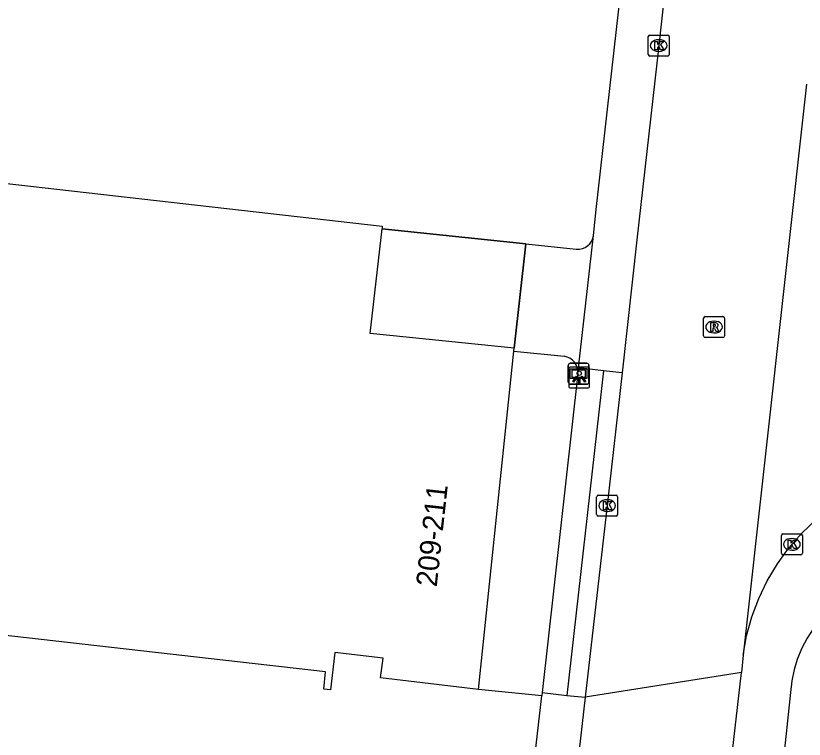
# Model space of a CAD drawing. Extents: x 161389 to 162585, y 388479 to 389761.
# Drawn here: x 162316.81 to 162354.51, y 388781.78 to 388816.39 of the extents above; entities that cross this region are included whole.
import ezdxf

# ---------------------------------------------------------------- set-up
doc = ezdxf.new("R2010")
doc.units = 0
for name, color, linetype in [('IMGEO_Berm_groen', 7, 'Continuous'), ('IMGEO_Groenvoorziening', 7, 'Continuous'), ('IMGEO_Hek', 7, 'Continuous'), ('IMGEO_Kolk', 7, 'Continuous'), ('IMGEO_Lichtpunt', 7, 'Continuous'), ('IMGEO_Pand', 7, 'Continuous'), ('IMGEO_Pand_nummerreeks', 7, 'Continuous'), ('IMGEO_Rijbaan_lokaal_gesloten', 7, 'Continuous'), ('IMGEO_Rioolput', 7, 'Continuous'), ('IMGEO_Verklikker', 7, 'Continuous'), ('IMGEO_Voetpad_open', 7, 'Continuous')]:
    doc.layers.add(name, color=color, linetype=linetype)

msp = doc.modelspace()

# ---------------------------------------------------------------- linework, layer by layer
at = {"layer": 'IMGEO_Berm_groen'}
msp.add_lwpolyline([(162353.858, 388784.024), (162350.241, 388750), (162349.171, 388742.638), (162348.615, 388740.14)], dxfattribs=at)
msp.add_arc((162359.605, 388783.689), 5.757, 90.5023, 176.6641, dxfattribs=at)
at = {"layer": 'IMGEO_Groenvoorziening'}
msp.add_lwpolyline([(162341.961, 388783.856), (162338.936, 388784.171)], dxfattribs=at)
at = {"layer": 'IMGEO_Hek'}
for points in [[(162341.192, 388805.477), (162334.321, 388806.194)], [(162340.638, 388800.493), (162341.192, 388805.477)]]:
    msp.add_lwpolyline(points, dxfattribs=at)
at = {"layer": 'IMGEO_Kolk'}
for p, q in [((162347.048, 388814.54), (162347.048, 388815.392)), ((162347.123, 388815.466), (162347.975, 388815.466)), ((162348.049, 388815.392), (162348.049, 388814.54)), ((162347.536, 388815.246), (162347.561, 388815.246)), ((162347.559, 388814.686), (162347.534, 388814.686)), ((162347.975, 388814.466), (162347.123, 388814.466)), ((162344.582, 388792.535), (162344.582, 388793.387)), ((162344.657, 388793.461), (162345.509, 388793.461)), ((162345.07, 388793.241), (162345.095, 388793.241)), ((162345.583, 388793.387), (162345.583, 388792.535)), ((162345.509, 388792.461), (162344.657, 388792.461)), ((162345.093, 388792.681), (162345.068, 388792.681)), ((162353.416, 388790.681), (162353.416, 388791.533)), ((162353.491, 388791.607), (162354.343, 388791.607)), ((162353.904, 388791.387), (162353.929, 388791.387)), ((162354.417, 388791.533), (162354.417, 388790.681)), ((162354.343, 388790.607), (162353.491, 388790.607)), ((162353.927, 388790.827), (162353.902, 388790.827))]:
    msp.add_line(p, q, dxfattribs=at)
for points in [[(162347.048, 388814.54), (162347.048, 388815.392)], [(162347.123, 388815.466), (162347.975, 388815.466)], [(162348.049, 388815.392), (162348.049, 388814.54)], [(162347.369, 388815.166), (162347.492, 388815.166), (162347.492, 388815.015), (162347.622, 388815.166), (162347.786, 388815.166), (162347.64, 388815.015), (162347.793, 388814.766), (162347.641, 388814.766), (162347.556, 388814.93), (162347.492, 388814.863), (162347.492, 388814.766), (162347.369, 388814.766), (162347.369, 388815.166)], [(162347.975, 388814.466), (162347.123, 388814.466)], [(162344.582, 388792.535), (162344.582, 388793.387)], [(162344.657, 388793.461), (162345.509, 388793.461)], [(162344.903, 388793.161), (162345.026, 388793.161), (162345.026, 388793.01), (162345.156, 388793.161), (162345.32, 388793.161), (162345.174, 388793.01), (162345.327, 388792.761), (162345.175, 388792.761), (162345.09, 388792.925), (162345.026, 388792.858), (162345.026, 388792.761), (162344.903, 388792.761), (162344.903, 388793.161)], [(162345.583, 388793.387), (162345.583, 388792.535)], [(162345.509, 388792.461), (162344.657, 388792.461)], [(162353.416, 388790.681), (162353.416, 388791.533)], [(162353.491, 388791.607), (162354.343, 388791.607)], [(162353.737, 388791.307), (162353.86, 388791.307), (162353.86, 388791.156), (162353.99, 388791.307), (162354.154, 388791.307), (162354.008, 388791.156), (162354.161, 388790.907), (162354.009, 388790.907), (162353.924, 388791.071), (162353.86, 388791.004), (162353.86, 388790.907), (162353.737, 388790.907), (162353.737, 388791.307)], [(162354.417, 388791.533), (162354.417, 388790.681)], [(162354.343, 388790.607), (162353.491, 388790.607)]]:
    msp.add_lwpolyline(points, dxfattribs=at)
for centre, start, end in [((162347.125, 388815.39), 91.552, 178.448), ((162347.125, 388815.39), 91.552, 178.448), ((162347.973, 388815.39), 1.552, 88.448), ((162347.973, 388815.39), 1.552, 88.448), ((162347.125, 388814.542), 181.552, 268.448), ((162347.125, 388814.542), 181.552, 268.448), ((162347.973, 388814.542), 271.552, 358.448), ((162347.973, 388814.542), 271.552, 358.448), ((162344.659, 388793.385), 91.552, 178.448), ((162344.659, 388793.385), 91.552, 178.448), ((162345.507, 388793.385), 1.552, 88.448), ((162345.507, 388793.385), 1.552, 88.448), ((162344.659, 388792.537), 181.552, 268.448), ((162344.659, 388792.537), 181.552, 268.448), ((162345.507, 388792.537), 271.552, 358.448), ((162345.507, 388792.537), 271.552, 358.448), ((162353.493, 388791.531), 91.552, 178.448), ((162353.493, 388791.531), 91.552, 178.448), ((162354.341, 388791.531), 1.552, 88.448), ((162354.341, 388791.531), 1.552, 88.448), ((162353.493, 388790.683), 181.552, 268.448), ((162353.493, 388790.683), 181.552, 268.448), ((162354.341, 388790.683), 271.552, 358.448), ((162354.341, 388790.683), 271.552, 358.448)]:
    msp.add_arc(centre, 0.0765, start, end, dxfattribs=at)
for centre, major_axis, ratio, start_param, end_param in [((162347.535, 388814.966), (-0.387, 0.002), 0.722429, 4.712389, 7.853982), ((162347.56, 388814.966), (-0.39, 0.002), 0.717154, 1.570796, 4.712389), ((162345.069, 388792.961), (-0.387, 0.002), 0.722429, 4.712389, 7.853982), ((162345.094, 388792.961), (-0.39, 0.002), 0.717154, 1.570796, 4.712389), ((162353.903, 388791.107), (-0.387, 0.002), 0.722429, 4.712389, 7.853982), ((162353.928, 388791.107), (-0.39, 0.002), 0.717154, 1.570796, 4.712389)]:
    msp.add_ellipse(centre, major_axis=major_axis, ratio=ratio, start_param=start_param, end_param=end_param, dxfattribs=at)
at = {"layer": 'IMGEO_Lichtpunt'}
for p, q in [((162344.15, 388799.585), (162343.342, 388799.585)), ((162344.15, 388799.585), (162343.342, 388799.585)), ((162343.248, 388799.49), (162343.248, 388798.683)), ((162343.248, 388799.49), (162343.248, 388798.683)), ((162344.244, 388798.683), (162344.244, 388799.49)), ((162344.244, 388798.683), (162344.244, 388799.49)), ((162343.342, 388798.589), (162344.15, 388798.589)), ((162343.342, 388798.589), (162344.15, 388798.589))]:
    msp.add_line(p, q, dxfattribs=at)
for points in [[(162343.622, 388799.154), (162343.661, 388799.126), (162343.473, 388798.864), (162343.435, 388798.891), (162343.622, 388799.154)], [(162343.724, 388799.106), (162343.771, 388799.106), (162343.771, 388798.784), (162343.724, 388798.784), (162343.724, 388799.106)], [(162343.834, 388799.126), (162343.872, 388799.153), (162344.059, 388798.891), (162344.02, 388798.863), (162343.834, 388799.126)]]:
    msp.add_lwpolyline(points, dxfattribs=at)
msp.add_circle((162343.747, 388799.288), 0.0994, dxfattribs=at)
for centre, start, end in [((162343.342, 388799.49), 90, 180), ((162343.342, 388799.49), 90, 180), ((162344.15, 388799.49), 0, 90), ((162344.15, 388799.49), 0, 90), ((162343.342, 388798.683), 180, 270), ((162343.342, 388798.683), 180, 270), ((162344.15, 388798.683), 270, 0), ((162344.15, 388798.683), 270, 360)]:
    msp.add_arc(centre, 0.0946, start, end, dxfattribs=at)
at = {"layer": 'IMGEO_Pand'}
for points in [[(162338.936, 388784.171), (162334.24, 388784.715), (162334.379, 388785.658), (162332.058, 388785.932), (162331.85, 388784.151), (162331.535, 388784.179), (162331.623, 388785.008), (162280.589, 388790.807), (162283.02, 388812.167), (162334.332, 388806.326), (162334.321, 388806.194)], [(162340.638, 388800.493), (162333.756, 388801.193), (162334.321, 388806.194)], [(162338.936, 388784.171), (162340.623, 388800.353)], [(162340.623, 388800.353), (162340.638, 388800.493)]]:
    msp.add_lwpolyline(points, dxfattribs=at)
at = {"layer": 'IMGEO_Rijbaan_lokaal_gesloten'}
for points in [[(162348.397, 388822.686), (162347.549, 388814.966), (162346.508, 388805.67), (162345.796, 388799.312)], [(162354.609, 388813.12), (162351.586, 388785.803)], [(162345.796, 388799.312), (162345.085, 388792.96), (162344.038, 388783.802)], [(162351.586, 388785.803), (162351.754, 388786.729), (162352.005, 388787.636), (162352.335, 388788.517), (162352.742, 388789.365), (162353.224, 388790.173), (162353.776, 388790.935), (162354.394, 388791.645), (162355.073, 388792.296), (162355.807, 388792.885), (162356.591, 388793.405), (162357.418, 388793.853), (162358.282, 388794.226), (162359.176, 388794.52), (162360.092, 388794.733), (162362.478, 388794.795), (162363.253, 388794.734), (162365.122, 388794.512)], [(162351.586, 388785.803), (162351.507, 388784.973)], [(162351.507, 388784.973), (162344.038, 388783.802)], [(162346.266, 388739.136), (162347.508, 388750), (162351.507, 388784.973)], [(162344.038, 388783.802), (162342.836, 388773.285), (162342.124, 388767.05)]]:
    msp.add_lwpolyline(points, dxfattribs=at)
at = {"layer": 'IMGEO_Rioolput'}
for p, q in [((162349.694, 388801.077), (162349.694, 388801.929)), ((162349.769, 388802.003), (162350.621, 388802.003)), ((162350.695, 388801.929), (162350.695, 388801.077)), ((162350.182, 388801.783), (162350.207, 388801.783)), ((162350.205, 388801.223), (162350.18, 388801.223)), ((162350.621, 388801.003), (162349.769, 388801.003))]:
    msp.add_line(p, q, dxfattribs=at)
for points in [[(162349.694, 388801.077), (162349.694, 388801.929)], [(162349.769, 388802.003), (162350.621, 388802.003)], [(162350.695, 388801.929), (162350.695, 388801.077)], [(162350.283, 388801.701), (162350.031, 388801.703), (162350.031, 388801.303)], [(162350.031, 388801.303), (162350.155, 388801.303), (162350.155, 388801.465), (162350.166, 388801.465)], [(162350.209, 388801.622), (162350.155, 388801.622), (162350.155, 388801.541)], [(162350.155, 388801.541), (162350.207, 388801.541)], [(162350.213, 388801.436), (162350.284, 388801.303), (162350.424, 388801.303), (162350.359, 388801.429)], [(162350.621, 388801.003), (162349.769, 388801.003)]]:
    msp.add_lwpolyline(points, dxfattribs=at)
for centre, radius, start, end in [((162349.771, 388801.927), 0.0765, 91.552, 178.448), ((162349.771, 388801.927), 0.0765, 91.552, 178.448), ((162350.619, 388801.927), 0.0765, 1.552, 88.448), ((162350.619, 388801.927), 0.0765, 1.552, 88.448), ((162350.165, 388801.412), 0.0533, 26.0293, 88.6989), ((162350.191, 388801.73), 0.19, 274.7715, 282.9687), ((162350.215, 388801.526), 0.0964, 77.0061, 93.1865), ((162350.229, 388801.583), 0.0378, 276.6634, 79.6772), ((162350.282, 388801.591), 0.109, 350.3612, 89.416), ((162350.28, 388801.591), 0.112, 277.5842, 350.9817), ((162350.264, 388801.376), 0.108, 29.5134, 73.7905), ((162349.771, 388801.079), 0.0765, 181.552, 268.448), ((162349.771, 388801.079), 0.0765, 181.552, 268.448), ((162350.619, 388801.079), 0.0765, 271.552, 358.448), ((162350.619, 388801.079), 0.0765, 271.552, 358.448)]:
    msp.add_arc(centre, radius, start, end, dxfattribs=at)
for centre, major_axis, ratio, start_param, end_param in [((162350.181, 388801.503), (-0.387, 0.002), 0.722429, 4.712389, 7.853982), ((162350.206, 388801.503), (-0.39, 0.002), 0.717154, 1.570796, 4.712389)]:
    msp.add_ellipse(centre, major_axis=major_axis, ratio=ratio, start_param=start_param, end_param=end_param, dxfattribs=at)
at = {"layer": 'IMGEO_Verklikker'}
for p, q in [((162343.221, 388798.867), (162343.221, 388799.667)), ((162343.221, 388799.667), (162343.221, 388798.867)), ((162343.321, 388799.767), (162344.111, 388799.767)), ((162344.111, 388799.767), (162343.321, 388799.767)), ((162344.211, 388799.667), (162344.211, 388798.867)), ((162344.211, 388798.867), (162344.211, 388799.667)), ((162344.111, 388798.767), (162343.321, 388798.767)), ((162343.321, 388798.767), (162344.111, 388798.767))]:
    msp.add_line(p, q, dxfattribs=at)
for points in [[(162343.322, 388799.499), (162344.11, 388799.499), (162344.11, 388799.035), (162343.322, 388799.035), (162343.322, 388799.499)], [(162343.387, 388799.434), (162343.387, 388799.1), (162344.045, 388799.1), (162344.045, 388799.434), (162343.387, 388799.434)]]:
    msp.add_lwpolyline(points, dxfattribs=at)
for centre, start, end in [((162343.321, 388799.667), 90, 180), ((162343.321, 388799.667), 90, 180), ((162344.111, 388799.667), 0, 90), ((162344.111, 388799.667), 360, 90), ((162343.321, 388798.867), 180, 270), ((162343.321, 388798.867), 180, 270), ((162344.111, 388798.867), 270, 0), ((162344.111, 388798.867), 270, 0)]:
    msp.add_arc(centre, 0.1, start, end, dxfattribs=at)
at = {"layer": 'IMGEO_Voetpad_open'}
for points in [[(162344.428, 388805.878), (162344.552, 388807.124), (162346.379, 388823.232)], [(162334.321, 388806.194), (162341.192, 388805.477)], [(162343.72, 388799.552), (162344.428, 388805.878)], [(162341.192, 388805.477), (162340.638, 388800.493)], [(162341.192, 388805.477), (162343.606, 388805.225)], [(162340.623, 388800.353), (162343.021, 388800.103)], [(162343.689, 388799.274), (162343.72, 388799.552)], [(162344.909, 388799.405), (162343.72, 388799.552)], [(162343.689, 388799.274), (162341.98, 388784.02)], [(162344.909, 388799.405), (162343.152, 388783.876)], [(162345.796, 388799.312), (162344.909, 388799.405)], [(162340.71, 388772.751), (162340.788, 388773.594), (162341.961, 388783.856)], [(162341.98, 388784.02), (162341.961, 388783.856)], [(162341.98, 388784.02), (162343.152, 388783.876)], [(162343.152, 388783.876), (162344.038, 388783.802)]]:
    msp.add_lwpolyline(points, dxfattribs=at)
for centre, radius, start, end in [((162343.683, 388805.972), 0.751, 264.1251, 352.8024), ((162342.918, 388799.336), 0.774, 355.386, 82.3371)]:
    msp.add_arc(centre, radius, start, end, dxfattribs=at)

# ---------------------------------------------------------------- texts
at = {"layer": 'IMGEO_Pand_nummerreeks'}
msp.add_text('209-211', height=1, rotation=83.7697, dxfattribs=at).set_placement((162336.934, 388789.048))

doc.saveas('drawing.dxf')
